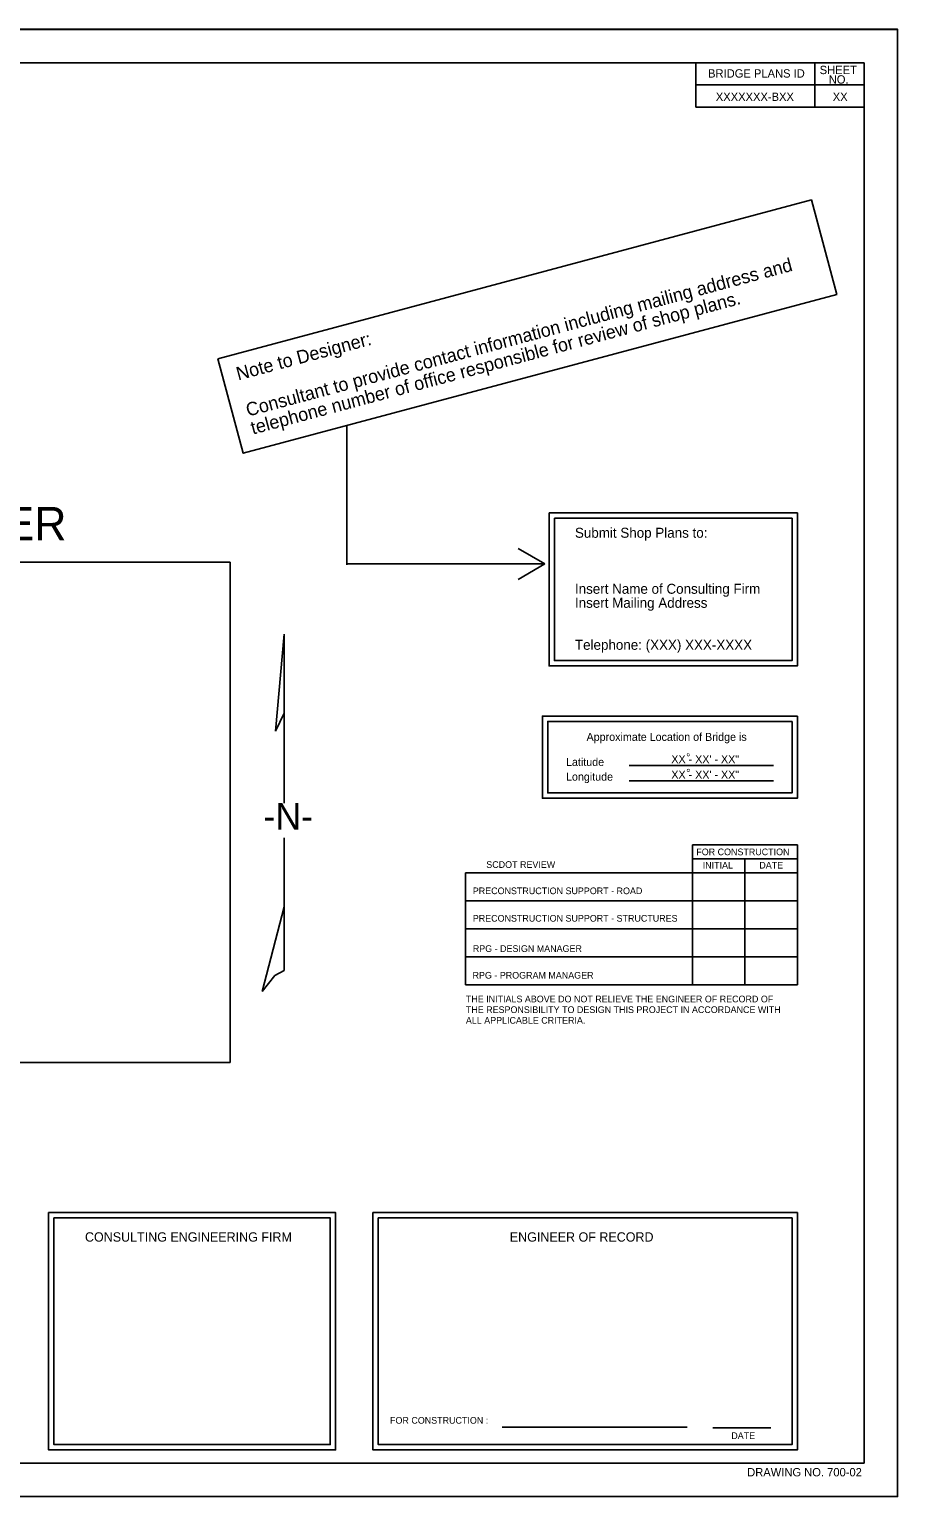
# Model space of a CAD drawing. Extents: x 0 to 3450, y -1150 to 1100.
# Drawn here: x 1050 to 1700, y 0 to 1100 of the extents above; entities that cross this region are included whole.
import ezdxf

# ---------------------------------------------------------------- set-up
doc = ezdxf.new("R2010")
doc.units = 0
for name, color, linetype in [('BR_AUTO DIMENSION', 7, 'Continuous'), ('BR_BORDER LINES', 7, 'Continuous'), ('BR_REBAR', 7, 'Continuous'), ('BR_TABLE LINES', 7, 'Continuous'), ('BR_TEXT', 7, 'Continuous'), ('Default', 7, 'Continuous'), ('RD_SHT_IplotShp', 7, 'Continuous')]:
    doc.layers.add(name, color=color, linetype=linetype)

msp = doc.modelspace()

# ---------------------------------------------------------------- linework, layer by layer
at = {"layer": 'BR_BORDER LINES'}
for p, q in [((0, 1100.1), (1700, 1100.1)), ((1675, 1075), (100, 1075)), ((1548.9, 1041.7), (1548.9, 1075)), ((1633.3, 1075), (1633.3, 1075)), ((1638, 1041.7), (1638, 1075)), ((1654.1, 1075), (1654.1, 1075)), ((1675, 25), (1675, 1075)), ((1548.9, 1058.5), (1675, 1058.5)), ((1548.9, 1041.7), (1675, 1041.7)), ((100, 25), (1675, 25)), ((0, 0.1), (1700, 0.1))]:
    msp.add_line(p, q, dxfattribs=at)
at = {"layer": 'BR_REBAR'}
for p, q in [((575, 700.6), (1200, 700.6)), ((1200, 700.6), (1200, 325.6)), ((575, 325.6), (1200, 325.6))]:
    msp.add_line(p, q, dxfattribs=at)
at = {"layer": 'BR_TABLE LINES'}
for p, q in [((1287.4, 802.9), (1287.4, 698.7)), ((1435.7, 699.3), (1415.7, 710.8)), ((1287.4, 699.3), (1435.7, 699.3)), ((1435.7, 699.3), (1415.7, 687.7))]:
    msp.add_line(p, q, dxfattribs=at)
msp.add_lwpolyline([(1190.9, 853.1), (1635.4, 972.2), (1654.4, 901.3), (1209.9, 782.2)], close=True, dxfattribs=at)
at = {"layer": 'Default'}
for p, q in [((1233.9, 573.8), (1240.6, 646.6)), ((1240.6, 646.6), (1240.6, 587.3)), ((1240.6, 587.3), (1233.9, 573.8)), ((1240.6, 587.3), (1240.6, 546.2)), ((1240.6, 546.2), (1240.6, 520)), ((1498.9, 548.1), (1607, 548.1)), ((1498.9, 536.6), (1607, 536.6)), ((1240.6, 493.9), (1240.6, 442.1)), ((1546.3, 383.7), (1546.3, 488.7)), ((1546.3, 488.7), (1625, 488.7)), ((1625, 488.7), (1625, 383.7)), ((1546.3, 478.2), (1625, 478.2)), ((1585.6, 478.2), (1585.6, 383.7)), ((1376.3, 467.7), (1625, 467.7)), ((1376.3, 383.7), (1376.3, 467.7)), ((1224.1, 378.6), (1240.6, 442.1)), ((1240.6, 442.1), (1240.6, 434.2)), ((1376.3, 446.7), (1625, 446.7)), ((1240.6, 434.2), (1240.6, 394.5)), ((1376.3, 425.7), (1625, 425.7)), ((1376.3, 404.7), (1625, 404.7)), ((1376.3, 383.7), (1625, 383.7)), ((1403.8, 52.2), (1542.4, 52.2)), ((1561.5, 51.6), (1605, 51.6))]:
    msp.add_line(p, q, dxfattribs=at)
for points in [[(1438.9, 737.5), (1625, 737.5), (1625, 622.8), (1438.9, 622.8)], [(1442.9, 733.5), (1621, 733.5), (1621, 626.8), (1442.9, 626.8)], [(1625, 585.2), (1433.9, 585.2), (1433.9, 523.6), (1625, 523.6)], [(1621, 581.2), (1437.9, 581.2), (1437.9, 527.6), (1621, 527.6)], [(1064, 213), (1279, 213), (1279, 35), (1064, 35)], [(1307, 213), (1625, 213), (1625, 35), (1307, 35)], [(1068, 209), (1275, 209), (1275, 39), (1068, 39)], [(1311, 209), (1621, 209), (1621, 39), (1311, 39)]]:
    msp.add_lwpolyline(points, close=True, dxfattribs=at)
msp.add_lwpolyline([(1240.6, 394.5), (1233.5, 390.6), (1224.1, 378.6)], dxfattribs=at)
at = {"layer": 'RD_SHT_IplotShp'}
msp.add_lwpolyline([(0, 1100), (1700, 1100), (1700, 0), (0, 0)], close=True, dxfattribs=at)

# ---------------------------------------------------------------- texts
at = {"layer": 'BR_AUTO DIMENSION'}
msp.add_text('DRAWING NO. 700-02', height=6.25, dxfattribs=at).set_placement((1587.3, 15.2))
at = {"layer": 'BR_TEXT'}
for s, height, p in [('BRIDGE PLANS ID', 6.25, (1558, 1063.9)), ('SHEET', 6.25, (1641.6, 1066.5)), ('NO.', 6.25, (1648.4, 1059.4)), ('XXXXXXX-BXX', 6.25, (1563.8, 1046.4)), ('XX', 6.25, (1651.4, 1046.4)), ('REPLACE BRIDGE OVER', 25, (679.9, 717))]:
    msp.add_text(s, height=height, dxfattribs=at).set_placement(p)
for s, p in [('Consultant to provide contact information including mailing address and  ', (1213.4, 809.7)), ('telephone number of office responsible for review of shop plans.', (1217, 796.2)), ('Note to Designer:', (1206.1, 836.8))]:
    msp.add_text(s, height=10, rotation=15, dxfattribs=at).set_placement(p)
at = {"layer": 'Default'}
for s, height, p in [('Submit Shop Plans to:', 7.5, (1458.3, 718.9)), ('Insert Name of Consulting Firm', 7.5, (1458.3, 676.9)), ('Insert Mailing Address', 7.5, (1458.3, 666.4)), ('Telephone: (XXX) XXX-XXXX', 7.5, (1458.3, 634.9)), ('Approximate Location of Bridge is', 6, (1467, 566.6)), ('Latitude', 6, (1451.6, 547.8)), ('XX - XX\' - XX"', 6, (1530.5, 549.9)), ('%%d', 6, (1541.6, 551.3)), ('Longitude', 6, (1451.6, 536.8)), ('XX - XX\' - XX"', 6, (1530.5, 538.3)), ('%%d', 6, (1541.6, 539.6)), ('-N-', 20, (1225, 500.1)), ('SCDOT REVIEW', 4.998, (1391.9, 471.4)), ('PRECONSTRUCTION SUPPORT - ROAD', 4.998, (1381.8, 451.7)), ('PRECONSTRUCTION SUPPORT - STRUCTURES', 4.998, (1381.8, 431.1)), ('RPG - DESIGN MANAGER', 4.998, (1381.8, 408.4)), ('RPG - PROGRAM MANAGER', 4.998, (1381.6, 388.4)), ('THE INITIALS ABOVE DO NOT RELIEVE THE ENGINEER OF RECORD OF ', 4.998, (1376.6, 370.6)), ('THE RESPONSIBILITY TO DESIGN THIS PROJECT IN ACCORDANCE WITH ', 4.998, (1376.6, 362.6)), ('ALL APPLICABLE CRITERIA.', 4.998, (1376.6, 354.6)), ('CONSULTING ENGINEERING FIRM', 7, (1091.3, 191.2)), ('ENGINEER OF RECORD', 7, (1409.5, 191.2)), ('FOR CONSTRUCTION :', 5, (1319.8, 54.7)), ('DATE', 5, (1575.4, 43.2))]:
    msp.add_text(s, height=height, dxfattribs=at).set_placement(p)
for s, height, p in [('FOR CONSTRUCTION', 4.998, (1549.2, 480.9)), ('INITIAL', 5, (1554, 470.9)), ('DATE', 5, (1596.4, 470.9))]:
    msp.add_text(s, height=height, rotation=360, dxfattribs=at).set_placement(p)

doc.saveas('drawing.dxf')
